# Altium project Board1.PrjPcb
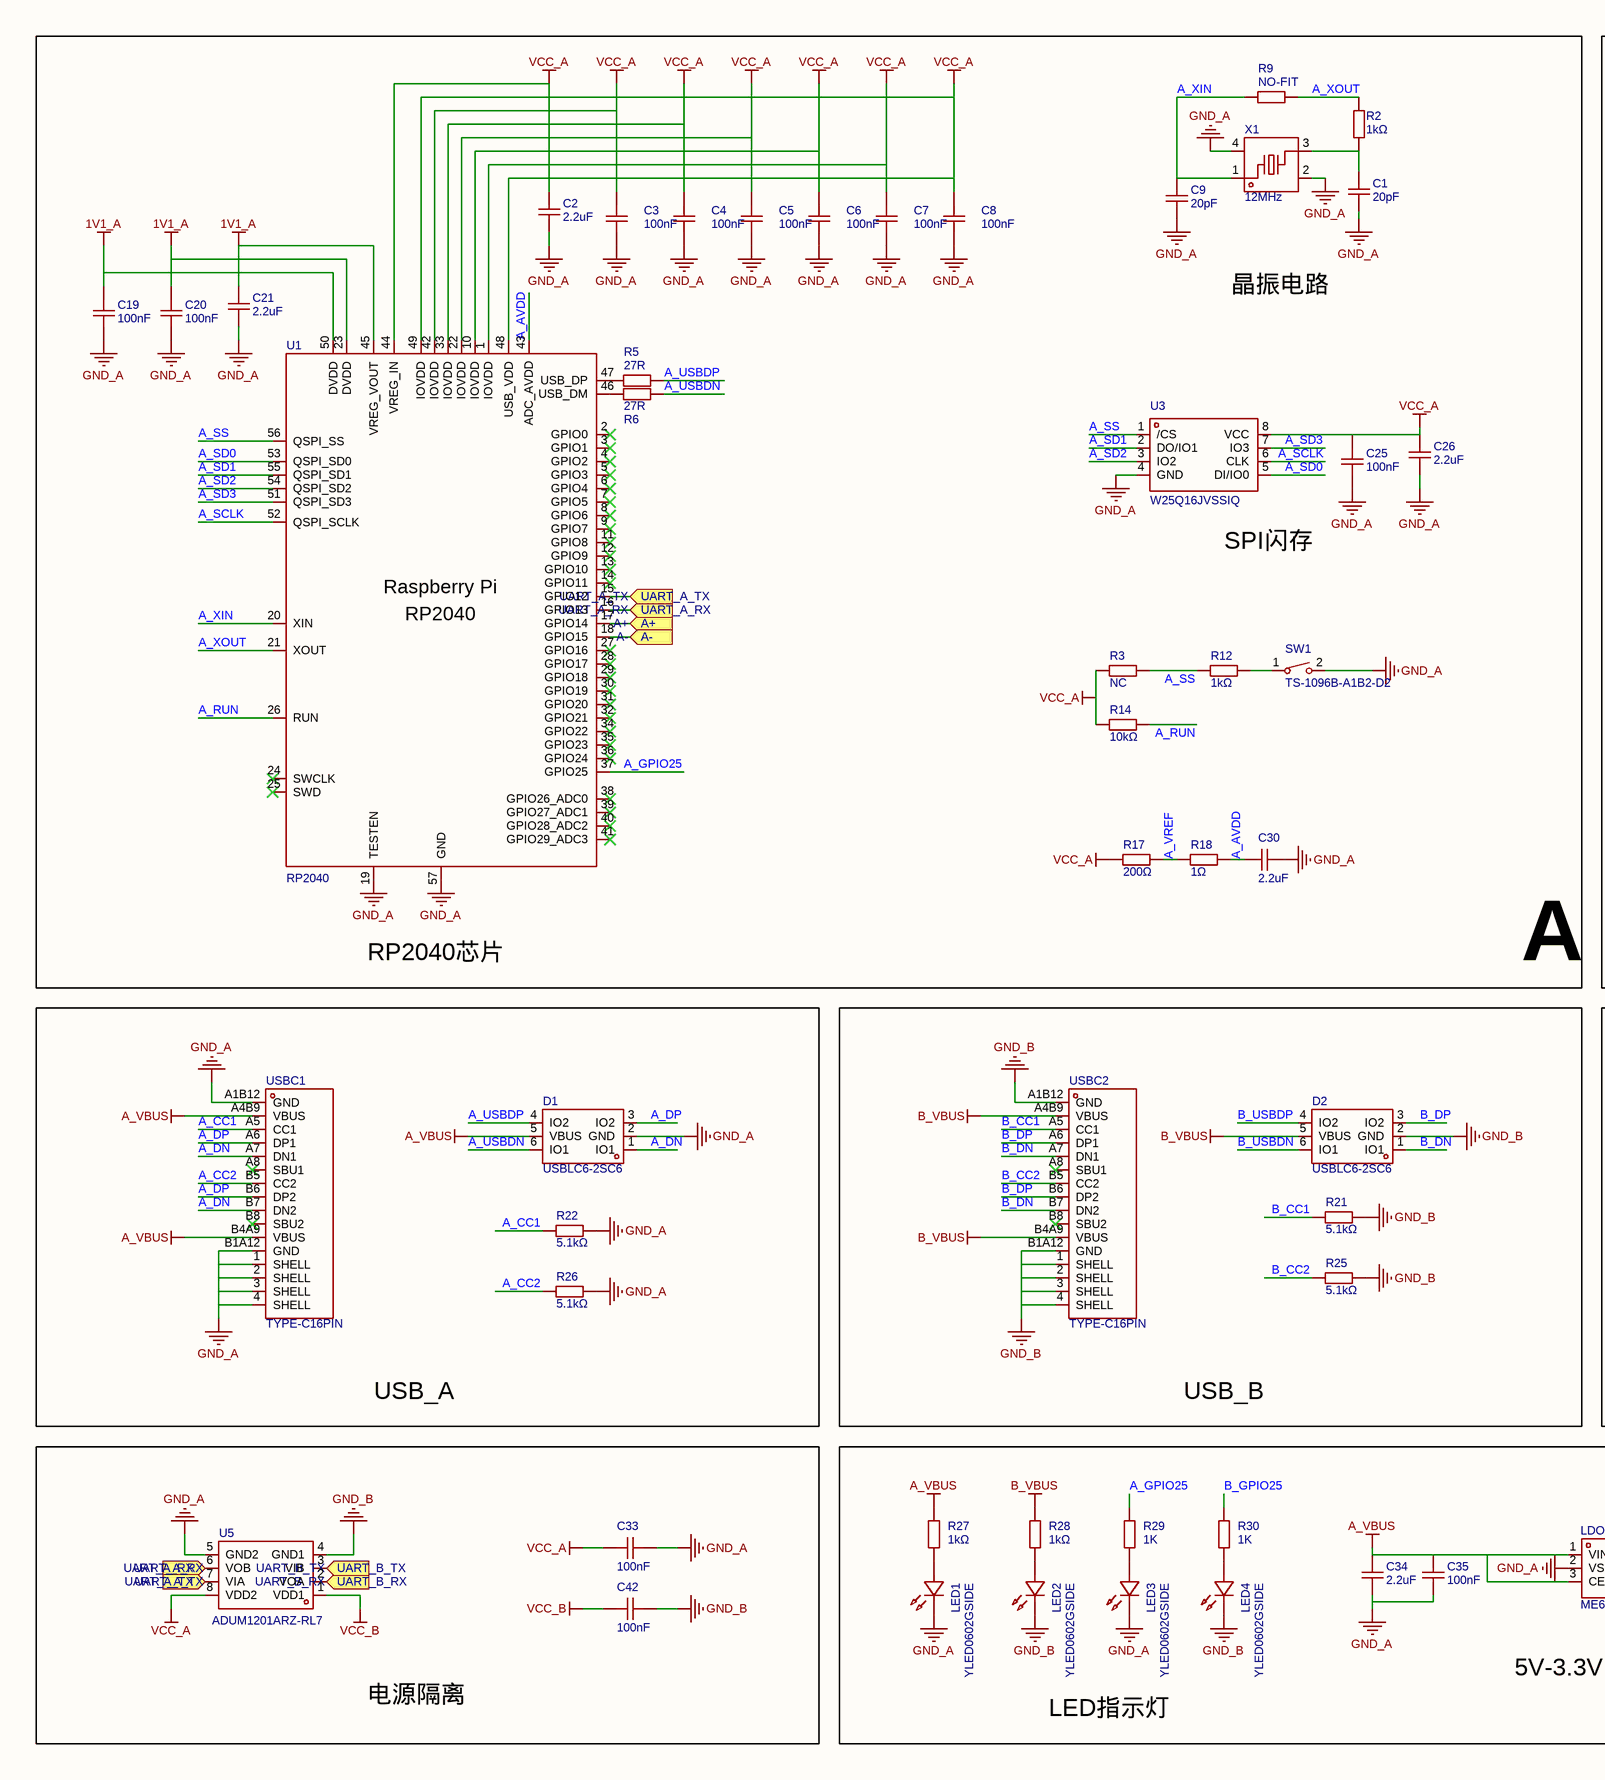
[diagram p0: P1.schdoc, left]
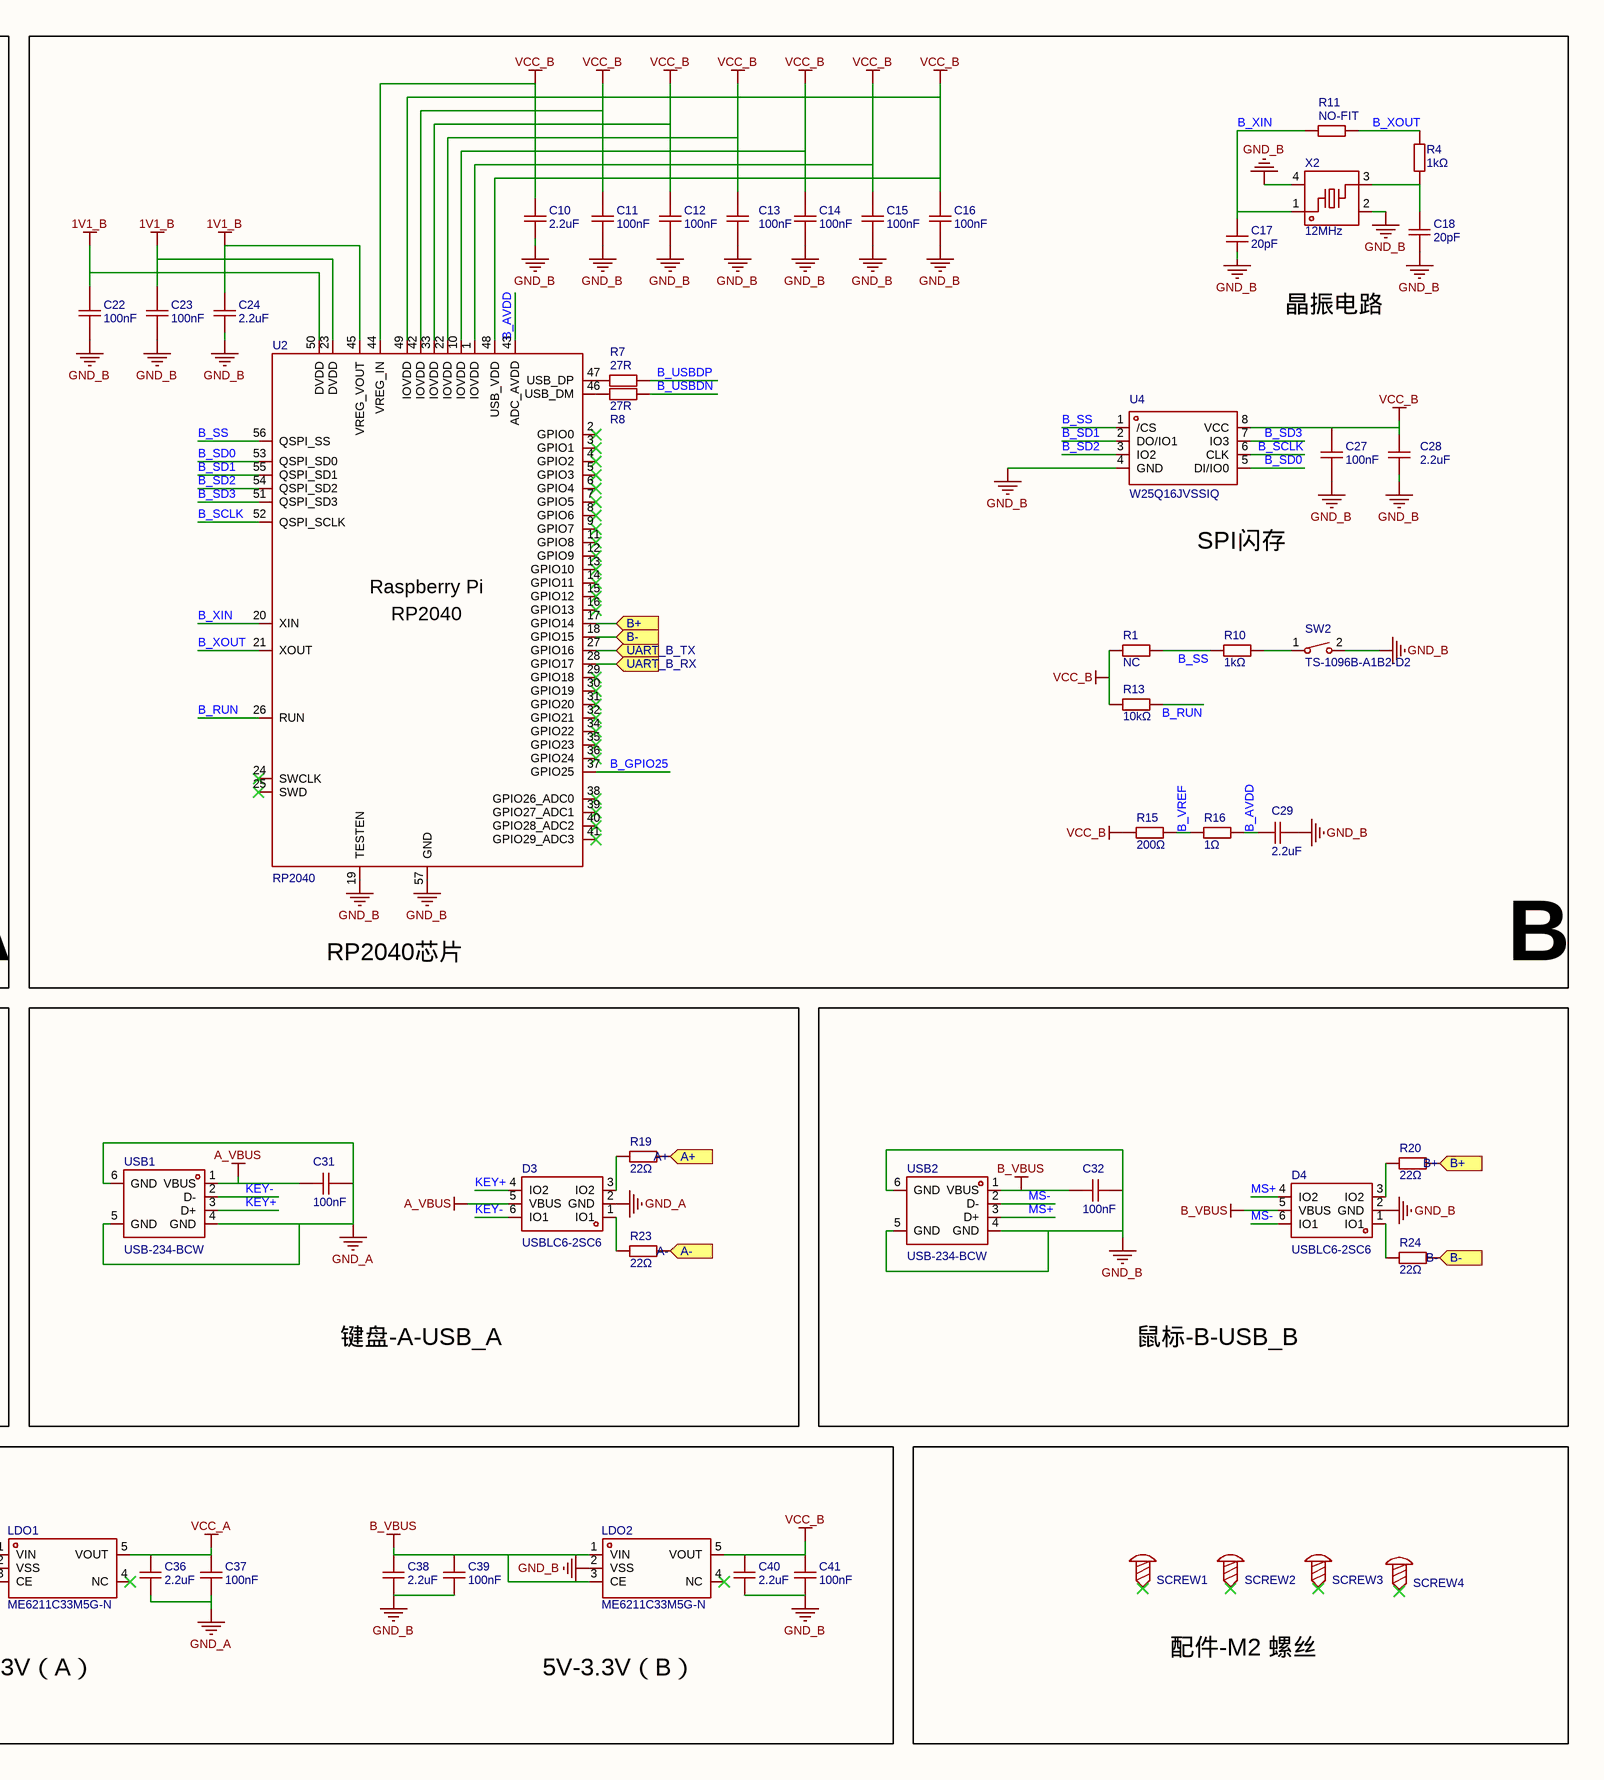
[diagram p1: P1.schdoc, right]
1 sheet, 99 parts. Net scope: flat (ports and power ports of the same name join across sheets).
Board file: PCB1.pcbdoc

## Sheet P1.schdoc
size 594 x 421 mm; Symbol: Sheet-Symbol_A4; Company: 嘉立创EDA; Version: V1.0; Page Size: A4; @Project Name: DESKHOP键盘鼠标共享器; @Page Count: 1; @Update Date: 2026-10-31; @Create Date: 2026-10-31; @Schematic Name: Schematic1; @Page No: 1; @Page Name: P1; Device: Sheet-Symbol_A4

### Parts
C1  20pF  [C0603]
C2  value 2.2uF  [C0603]  (hidden comment: CL10A225KO8NNNC)
C3  value 100nF  [C0603]  (hidden comment: CC0603KRX7R9BB104)
C4  value 100nF  [C0603]  (hidden comment: CC0603KRX7R9BB104)
C5  value 100nF  [C0603]  (hidden comment: CC0603KRX7R9BB104)
C6  value 100nF  [C0603]  (hidden comment: CC0603KRX7R9BB104)
C7  value 100nF  [C0603]  (hidden comment: CC0603KRX7R9BB104)
C8  value 100nF  [C0603]  (hidden comment: CC0603KRX7R9BB104)
C9  20pF  [C0603]
C10  value 2.2uF  [C0603]  (hidden comment: CL10A225KO8NNNC)
C11  value 100nF  [C0603]  (hidden comment: CC0603KRX7R9BB104)
C12  value 100nF  [C0603]  (hidden comment: CC0603KRX7R9BB104)
C13  value 100nF  [C0603]  (hidden comment: CC0603KRX7R9BB104)
C14  value 100nF  [C0603]  (hidden comment: CC0603KRX7R9BB104)
C15  value 100nF  [C0603]  (hidden comment: CC0603KRX7R9BB104)
C16  value 100nF  [C0603]  (hidden comment: CC0603KRX7R9BB104)
C17  20pF  [C0603]
C18  20pF  [C0603]
C19  value 100nF  [C0603]  (hidden comment: CC0603KRX7R9BB104)
C20  100nF  [C0603]
C21  value 2.2uF  [C0603]  (hidden comment: CL10A225KO8NNNC)
C22  value 100nF  [C0603]  (hidden comment: CC0603KRX7R9BB104)
C23  value 100nF  [C0603]  (hidden comment: CC0603KRX7R9BB104)
C24  value 2.2uF  [C0603]  (hidden comment: CL10A225KO8NNNC)
C25  value 100nF  [C0603]  (hidden comment: CC0603KRX7R9BB104)
C26  value 2.2uF  [C0603]  (hidden comment: CL10A225KO8NNNC)
C27  value 100nF  [C0603]  (hidden comment: CC0603KRX7R9BB104)
C28  value 2.2uF  [C0603]  (hidden comment: CL10A225KO8NNNC)
C29  value 2.2uF  [C0603]  (hidden comment: CL10A225KO8NNNC)
C30  value 2.2uF  [C0603]  (hidden comment: CL10A225KO8NNNC)
C31  value 100nF  [C0603]  (hidden comment: CC0603KRX7R9BB104)
C32  value 100nF  [C0603]  (hidden comment: CC0603KRX7R9BB104)
C33  100nF  [C0603]
C34  2.2uF  [C0603]
C35  100nF  [C0603]
C36  2.2uF  [C0603]
C37  100nF  [C0603]
C38  2.2uF  [C0603]
C39  100nF  [C0603]
C40  2.2uF  [C0603]
C41  100nF  [C0603]
C42  100nF  [C0603]
D1  USBLC6-2SC6  [SOT-23-6_L2.9-W1.6-P0.95-LS2.8-BL]
D2  USBLC6-2SC6  [SOT-23-6_L2.9-W1.6-P0.95-LS2.8-BL]
D3  USBLC6-2SC6  [SOT-23-6_L2.9-W1.6-P0.95-LS2.8-BL]
D4  USBLC6-2SC6  [SOT-23-6_L2.9-W1.6-P0.95-LS2.8-BL]
LDO1  ME6211C33M5G-N  [SOT-23-5_L3.0-W1.7-P0.95-LS2.8-BR]
LDO2  ME6211C33M5G-N  [SOT-23-5_L3.0-W1.7-P0.95-LS2.8-BR]
LED1  YLED0602GSIDE  [LED-SMD_L1.6-W1.1-R-RD_GREEN]
LED2  YLED0602GSIDE  [LED-SMD_L1.6-W1.1-R-RD_GREEN]
LED3  YLED0602GSIDE  [LED-SMD_L1.6-W1.1-R-RD_GREEN]
LED4  YLED0602GSIDE  [LED-SMD_L1.6-W1.1-R-RD_GREEN]
R1  value NC  [R0603]  (hidden comment: 0603WAF0000T5E)
R2  1kΩ  [R0603]
R3  value NC  [R0603]  (hidden comment: 0603WAF0000T5E)
R4  1kΩ  [R0603]
R5  27R  [R0603]
R6  27R  [R0603]
R7  27R  [R0603]
R8  27R  [R0603]
R9  NO-FIT  [R0603]
R10  value 1kΩ  [R0603]  (hidden comment: RC0603FR-071KL)
R11  NO-FIT  [R0603]
R12  value 1kΩ  [R0603]  (hidden comment: RC0603FR-071KL)
R13  value 10kΩ  [R0603]  (hidden comment: 0603WAF1002T5E)
R14  value 10kΩ  [R0603]  (hidden comment: 0603WAF1002T5E)
R15  value 200Ω  [R0603]  (hidden comment: 0603WAF2000T5E)
R16  value 1Ω  [R0603]  (hidden comment: 0603WAF100KT5E)
R17  value 200Ω  [R0603]  (hidden comment: 0603WAF2000T5E)
R18  value 1Ω  [R0603]  (hidden comment: 0603WAF100KT5E)
R19  22Ω  [R0603]
R20  22Ω  [R0603]
R21  value 5.1kΩ  [R0603]  (hidden comment: 0603WAF5101T5E)
R22  value 5.1kΩ  [R0603]  (hidden comment: 0603WAF5101T5E)
R23  22Ω  [R0603]
R24  22Ω  [R0603]
R25  value 5.1kΩ  [R0603]  (hidden comment: 0603WAF5101T5E)
R26  value 5.1kΩ  [R0603]  (hidden comment: 0603WAF5101T5E)
R27  1kΩ  [R0603]
R28  value 1kΩ  [R0603]  (hidden comment: 0603WAF1001T5E)
R29  1K  [R0603]
R30  1K  [R0603]
SCREW1  (no value)  [M2螺丝]
SCREW2  (no value)  [M2螺丝]
SCREW3  (no value)  [M2螺丝]
SCREW4  (no value)  [M2螺丝]
SW1  TS-1096B-A1B2-D2  [KEY-TH_L6.0-W3.3-P6.50]
SW2  TS-1096B-A1B2-D2  [KEY-TH_L6.0-W3.3-P6.50]
U1  Manufacturer Part: RP2040  [LQFN-56_L7.0-W7.0-P0.4-EP]  (hidden comment: RP2040_C2040)
U2  Manufacturer Part: RP2040  [LQFN-56_L7.0-W7.0-P0.4-EP]  (hidden comment: RP2040_C2040)
U3  W25Q16JVSSIQ  [SOIC-8_L5.3-W5.3-P1.27-LS8.0-BL]
U4  W25Q16JVSSIQ  [SOIC-8_L5.3-W5.3-P1.27-LS8.0-BL]
U5  ADUM1201ARZ-RL7  [SOIC-8_L4.9-W3.9-P1.27-LS6.0-BL]
USB1  USB-234-BCW  [USB-A-SMD_USB-234-BCW]
USB2  USB-234-BCW  [USB-A-SMD_USB-234-BCW]
USBC1  TYPE-C16PIN  [USB-C-SMD_TYPE-C16PIN]
USBC2  TYPE-C16PIN  [USB-C-SMD_TYPE-C16PIN]
X1  12MHz  [CRYSTAL-SMD_4P-L3.2-W2.5-BL]
X2  12MHz  [CRYSTAL-SMD_4P-L3.2-W2.5-BL]

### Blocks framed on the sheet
A: C1-C9 C19-C21 C25 C26 C30 R2 R3 R5 R6 R9 R12 R14 R17 R18 SW1 U1 U3 X1
B: C10-C18 C22-C24 C27-C29 R1 R4 R7 R8 R10 R11 R13 R15 R16 SW2 U2 U4 X2
USB_A: D1 R22 R26 USBC1
USB_B: D2 R21 R25 USBC2
键盘-A-USB_A: C31 D3 R19 R23 USB1
鼠标-B-USB_B: C32 D4 R20 R24 USB2
电源隔离: C33 C42 U5
配件-M2 螺丝: SCREW1-SCREW4

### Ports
A+ (in), A- (in), B+ (in), B- (in), UART_A_RX (in), UART_A_TX (in), UART_B_RX (in), UART_B_TX (in)

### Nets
1V1_A: C19.2 C20.2 C21.1 U1.23(DVDD) U1.45(VREG_VOUT) U1.50(DVDD)
1V1_B: C22.2 C23.2 C24.1 U2.23(DVDD) U2.45(VREG_VOUT) U2.50(DVDD)
A_VBUS: C31.2 C34.2 C35.2 D1.5(VBUS) D3.5(VBUS) LDO1.1(VIN) LDO1.3(CE) R27.2 USB1.1(VBUS) USBC1.A4B9(VBUS) USBC1.B4A9(VBUS)
B_VBUS: C32.2 C38.2 C39.2 D2.5(VBUS) D4.5(VBUS) LDO2.1(VIN) LDO2.3(CE) R28.2 USB2.1(VBUS) USBC2.A4B9(VBUS) USBC2.B4A9(VBUS)
GND_A: C1.2 C2.2 C3.1 C4.1 C5.1 C6.1 C7.1 C8.1 C9.2 C19.1 C20.1 C21.2 C25.1 C26.2 C30.2 C31.1 C33.2 C34.1 C35.1 C36.1 C37.1 D1.2(GND) D3.2(GND) LDO1.2(VSS) LED1.2(K) LED3.2(K) R22.2 R26.2 SW1.2 U1.19(TESTEN) U1.57(GND) U3.4(GND) U5.5(GND2) USB1.4(GND) USB1.5(GND) USB1.6(GND) USBC1.1(SHELL) USBC1.2(SHELL) USBC1.3(SHELL) USBC1.4(SHELL) USBC1.A1B12(GND) USBC1.B1A12(GND) X1.2(GND) X1.4(GND)
GND_B: C10.2 C11.1 C12.1 C13.1 C14.1 C15.1 C16.1 C17.2 C18.2 C22.1 C23.1 C24.2 C27.1 C28.2 C29.2 C32.1 C38.1 C39.1 C40.1 C41.1 C42.2 D2.2(GND) D4.2(GND) LDO2.2(VSS) LED2.2(K) LED4.2(K) R21.2 R25.2 SW2.2 U2.19(TESTEN) U2.57(GND) U4.4(GND) U5.4(GND1) USB2.4(GND) USB2.5(GND) USB2.6(GND) USBC2.1(SHELL) USBC2.2(SHELL) USBC2.3(SHELL) USBC2.4(SHELL) USBC2.A1B12(GND) USBC2.B1A12(GND) X2.2(GND) X2.4(GND)
VCC_A: C2.1 C3.2 C4.2 C5.2 C6.2 C7.2 C8.2 C25.2 C26.1 C33.1 C36.2 C37.2 LDO1.5(VOUT) R3.2 R14.2 R17.2 U1.1(IOVDD) U1.10(IOVDD) U1.22(IOVDD) U1.33(IOVDD) U1.42(IOVDD) U1.44(VREG_IN) U1.48(USB_VDD) U1.49(IOVDD) U3.8(VCC) U5.8(VDD2)
VCC_B: C10.1 C11.2 C12.2 C13.2 C14.2 C15.2 C16.2 C27.2 C28.1 C40.2 C41.2 C42.1 LDO2.5(VOUT) R1.2 R13.2 R15.2 U2.1(IOVDD) U2.10(IOVDD) U2.22(IOVDD) U2.33(IOVDD) U2.42(IOVDD) U2.44(VREG_IN) U2.48(USB_VDD) U2.49(IOVDD) U4.8(VCC) U5.1(VDD1)
A+: R19.2 U1.17(GPIO14) ; port A+
A-: R23.2 U1.18(GPIO15) ; port A-
A_AVDD: C30.1 R18.1 U1.43(ADC_AVDD)
A_CC1: R22.1 USBC1.A5(CC1)
A_CC2: R26.1 USBC1.B5(CC2)
A_DN: D1.1(IO1) USBC1.A7(DN1) USBC1.B7(DN2)
A_DP: D1.3(IO2) USBC1.A6(DP1) USBC1.B6(DP2)
A_GPIO25: R29.2 U1.37(GPIO25)
A_RUN: R14.1 U1.26(RUN)
A_SCLK: U1.52(QSPI_SCLK) U3.6(CLK)
A_SD0: U1.53(QSPI_SD0) U3.5(DI/IO0)
A_SD1: U1.55(QSPI_SD1) U3.2(DO/IO1)
A_SD2: U1.54(QSPI_SD2) U3.3(IO2)
A_SD3: U1.51(QSPI_SD3) U3.7(IO3)
A_SS: R3.1 R12.2 U1.56(QSPI_SS) U3.1(/CS)
A_USBDN: D1.6(IO1) R6.2
A_USBDP: D1.4(IO2) R5.2
A_VREF: R17.1 R18.2
A_XIN: C9.1 R9.1 U1.20(XIN) X1.1
A_XOUT: R2.2 R9.2 U1.21(XOUT)
B+: R20.2 U2.17(GPIO14) ; port B+
B-: R24.2 U2.18(GPIO15) ; port B-
B_AVDD: C29.1 R16.1 U2.43(ADC_AVDD)
B_CC1: R21.1 USBC2.A5(CC1)
B_CC2: R25.1 USBC2.B5(CC2)
B_DN: D2.1(IO1) USBC2.A7(DN1) USBC2.B7(DN2)
B_DP: D2.3(IO2) USBC2.A6(DP1) USBC2.B6(DP2)
B_GPIO25: R30.2 U2.37(GPIO25)
B_RUN: R13.1 U2.26(RUN)
B_SCLK: U2.52(QSPI_SCLK) U4.6(CLK)
B_SD0: U2.53(QSPI_SD0) U4.5(DI/IO0)
B_SD1: U2.55(QSPI_SD1) U4.2(DO/IO1)
B_SD2: U2.54(QSPI_SD2) U4.3(IO2)
B_SD3: U2.51(QSPI_SD3) U4.7(IO3)
B_SS: R1.1 R10.2 U2.56(QSPI_SS) U4.1(/CS)
B_USBDN: D2.6(IO1) R8.2
B_USBDP: D2.4(IO2) R7.2
B_VREF: R15.1 R16.2
B_XIN: C17.1 R11.1 U2.20(XIN) X2.1
B_XOUT: R4.2 R11.2 U2.21(XOUT)
KEY+: D3.4(IO2) USB1.3(D+)
KEY-: D3.6(IO1) USB1.2(D-)
MS+: D4.4(IO2) USB2.3(D+)
MS-: D4.6(IO1) USB2.2(D-)
UART_A_RX: U1.16(GPIO13) U5.6(VOB) ; port UART_A_RX
UART_A_TX: U1.15(GPIO12) U5.7(VIA) ; port UART_A_TX
UART_B_RX: U2.28(GPIO17) U5.2(VOA) ; port UART_B_RX
UART_B_TX: U2.27(GPIO16) U5.3(VIB) ; port UART_B_TX
NetC1_1: C1.1 R2.1 X1.3
NetC18_1: C18.1 R4.1 X2.3
NetD3_1: D3.1(IO1) R23.1
NetD3_3: D3.3(IO2) R19.1
NetD4_1: D4.1(IO1) R24.1
NetD4_3: D4.3(IO2) R20.1
NetLED1_1: LED1.1(A) R27.1
NetLED2_1: LED2.1(A) R28.1
NetLED3_1: LED3.1(A) R29.1
NetLED4_1: LED4.1(A) R30.1
NetR5_1: R5.1 U1.47(USB_DP)
NetR6_1: R6.1 U1.46(USB_DM)
NetR7_1: R7.1 U2.47(USB_DP)
NetR8_1: R8.1 U2.46(USB_DM)
NetR10_1: R10.1 SW2.1
NetR12_1: R12.1 SW1.1

Not connected (* = marked no-connect by the designer): LDO1 4(NC)*; LDO2 4(NC)*; SCREW1 1*; SCREW2 1*; SCREW3 1*; SCREW4 1*; U1 2(GPIO0)* 3(GPIO1)* 4(GPIO2)* 5(GPIO3)* 6(GPIO4)* 7(GPIO5)* 8(GPIO6)* 9(GPIO7)* 11(GPIO8)* 12(GPIO9)* 13(GPIO10)* 14(GPIO11)* 24(SWCLK)* 25(SWD)* 27(GPIO16)* 28(GPIO17)* 29(GPIO18)* 30(GPIO19)* 31(GPIO20)* 32(GPIO21)* 34(GPIO22)* 35(GPIO23)* 36(GPIO24)* 38(GPIO26_ADC0)* 39(GPIO27_ADC1)* 40(GPIO28_ADC2)* 41(GPIO29_ADC3)*; U2 2(GPIO0)* 3(GPIO1)* 4(GPIO2)* 5(GPIO3)* 6(GPIO4)* 7(GPIO5)* 8(GPIO6)* 9(GPIO7)* 11(GPIO8)* 12(GPIO9)* 13(GPIO10)* 14(GPIO11)* 15(GPIO12)* 16(GPIO13)* 24(SWCLK)* 25(SWD)* 29(GPIO18)* 30(GPIO19)* 31(GPIO20)* 32(GPIO21)* 34(GPIO22)* 35(GPIO23)* 36(GPIO24)* 38(GPIO26_ADC0)* 39(GPIO27_ADC1)* 40(GPIO28_ADC2)* 41(GPIO29_ADC3)*; USBC1 A8(SBU1)* B8(SBU2)*; USBC2 A8(SBU1)* B8(SBU2)*

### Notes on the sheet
- 晶振电路
- SPI闪存
- RP2040芯片
- LED指示灯
- 5V-3.3V（A）
- 5V-3.3V（B）

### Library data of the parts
C1 C9 C17 C18 = CC0603JRNPO9BN150: 容值:15pF;精度:±5%;额定电压:50V;材质(温度系数):NP0;; Manufacturer: YAGEO(国巨); 3D Model: ac125912035d415993ca9572d50418b1; 3D Model Transform: 62.992,31.496,0,0,0,0,0,0,0; Tolerance: ±5%; Voltage Rated: 50V; Temperature Coefficient: NP0; AddInBom: yes; ModelName: C0603_L1.6-W0.8-H0.8
C2 C10 C21 C24 C26 C28-C30 = CL10A225KO8NNNC: 容值:2.2uF;精度:±10%;额定电压:16V;材质(温度系数):X5R;; Manufacturer: SAMSUNG(三星); AddInBom: yes; ModelId: ac125912035d415993ca9572d50418b1; ModelName: C0603_L1.6-W0.8-H0.8; ModelTransform: 62.992,31.496,0,0,0,0,0,0,0; Tolerance: ±10%; Voltage Rated: 16V; Temperature Coefficient: X5R
C3-C8 C11-C16 C19 C22 C23 C25 C27 C31 C32 = CC0603KRX7R9BB104: 容值:100nF;精度:±10%;额定电压:50V;材质(温度系数):X7R;; Manufacturer: YAGEO(国巨); AddInBom: yes; ModelId: ac125912035d415993ca9572d50418b1; ModelName: C0603_L1.6-W0.8-H0.8; ModelTransform: 62.992,31.496,0,0,0,0,0,0,0; Tolerance: ±10%; Voltage Rated: 50V; Temperature Coefficient: X7R
C20 = CC0603KRX7R9BB104: 容值:100nF;精度:±10%;额定电压:50V;材质(温度系数):X7R;; Manufacturer: YAGEO(国巨); 3D Model: ac125912035d415993ca9572d50418b1; 3D Model Transform: 62.992,31.496,0,0,0,0,0,0,0; Tolerance: ±10%; Voltage Rated: 50V; Temperature Coefficient: X7R; AddInBom: yes; ModelName: C0603_L1.6-W0.8-H0.8
C33 C42 = CAP_0603: Symbol: Capacitance; 3D Model: ac125912035d415993ca9572d50418b1; 3D Model Transform: 62.992,31.496,0,0,0,0,0,0,0; ConvertToPcb: yes; ModelName: C0603_L1.6-W0.8-H0.8
C34 C36 C38 C40 = CL10A225KO8NNNC: 容值:2.2uF;精度:±10%;额定电压:16V;材质(温度系数):X5R;; Manufacturer: SAMSUNG(三星); 3D Model: ac125912035d415993ca9572d50418b1; 3D Model Transform: 62.992,31.496,0,0,0,0,0,0,0; Tolerance: ±10%; Voltage Rated: 16V; Temperature Coefficient: X5R; AddInBom: yes; ModelName: C0603_L1.6-W0.8-H0.8
C35 C37 C39 C41 = 0603B104K500NT: 容值:100nF;精度:±10%;额定电压:50V;材质(温度系数):X7R;; Manufacturer: FH(风华); 3D Model: ac125912035d415993ca9572d50418b1; 3D Model Transform: 62.992,31.496,0,0,0,0,0,0,0; Tolerance: ±10%; Voltage Rated: 50V; Temperature Coefficient: X7R; AddInBom: yes; ModelName: C0603_L1.6-W0.8-H0.8
D1-D4 = USBLC6-2SC6_C2827654: 极性:单向;反向截止电压(Vrwm):5V;钳位电压:12V;峰值脉冲电流(Ipp):6A;峰值脉冲功率(Ppp):150W;击穿电压:6V;; Manufacturer: TECH PUBLIC(台舟); AddInBom: yes; ModelId: 18da8f6c14a34920b3e136b5c401a1190819f05c4eef4c71ace90d822a990e87; ModelName: SOT-23-6_L2.9-W1.6-H1.5-LS2.8-P0.95; ModelTransform: 110.236,113.364,0,90,0,0,0.0005,0.0005,0; Polarity: 单向; Reverse Stand-Off Voltage (Vrwm): 5V; Clamping Voltage: 12V; Peak Pulse Current (Ipp): 6A; Peak Pulse Power Dissipation (Ppp): 150W; Voltage - Breakdown: 6V; Reverse Leakage Current (Ir): 80nA; Number of Channels: 双路; level of protection: IEC 61000-4-2；IEC 61000-4-4；IEC 61000-4-5; Type: ESD; Junction Capacitance: 0.35pF
LDO1 LDO2 = ME6211C33M5G-N: 输出类型:固定;输出极性:正;输出通道数:1;最大输入电压:6V;输出电压:3.3V;压差:260mV@(200mA);输出电流:500mA;电源纹波抑制比(PRSS):70dB@(1kHz),62dB@(10kHz);; Manufacturer: MICRONE(南京微盟); 3D Model: 0a2a1b8f50944f73965918ad6e5fe167; 3D Model Transform: 114.173,109.636,0,180,0,0,-0.863,0.863,0; Output Type: 固定; Output Polarity: 正; Number of Outputs: 1; Maximum Input Voltage: 6V; Output Voltage: 3.3V; Output Current: 500mA; AddInBom: yes; ModelName: SOT-23-5_L2.9-W1.6-H1.1-LS2.8-P0.95
LED1-LED4 = YLED0602GSIDE: 灯头类型:1mmx0.75mm方形灯头;发光颜色:翠绿色;正向压降(Vf):2.5V~3.1V;功率:100mW;测试电流:20mA;波长:534nm;二极管配置:独立二极管;透镜颜色:无色透明透镜;色温:-;发光强度:430mcd;发光角度:120°;载带方式:-;工作温度:-40℃~+85℃;; Manufacturer: YONGYUTAI(永裕泰); AddInBom: yes; ModelId: 2c28468672eb41c4bc812ce62ea4e6950819f05c4eef4c71ace90d822a990e87; ModelTransform: 63.7794,43.7007,0,0,0,0,0,11.22,0; Illumination Color: 翠绿色; Power(Watts): 100mW; Test Current: 20mA; Wavelength - Dominant: 534nm; Peak Wavelength: 525nm; Diode Configuration: 独立二极管; Lens Color: 无色透明透镜; Luminous Intensity: 430mcd; Viewing Angle: 120°
R1 R3 = 0603WAF0000T5E: 阻值:0Ω;精度:±1%;功率:100mW;电阻类型:厚膜电阻;; Manufacturer: UNI-ROYAL(厚声); Convert to PCB: no; ModelId: fc143cca1e79419f9cd78b61e9279f08; ModelTransform: 31.8897,63.7794,0,90,0,0,0,0,0; Tolerance: ±1%; Power(Watts): 100mW; Overload Voltage (Max): 75V
R2 R4 = RC0603FR-071KL: 电阻类型:厚膜电阻;阻值:1kΩ;精度:±1%;功率:100mW;温度系数:±100ppm/℃;最大工作电压:75V;工作温度范围:-55℃~+155℃;; Manufacturer: YAGEO(国巨); 3D Model: 3281a289d46d4bb1877be1eabd090e13; 3D Model Transform: 62.992,31.496,0,0,0,0,0,0,0; Tolerance: ±1%; Power(Watts): 100mW; Overload Voltage (Max): 75V; AddInBom: yes; ModelName: R0603_L1.6-W0.8-H0.8
R5-R8 = Res_0603: Symbol: 电阻; 3D Model: fc143cca1e79419f9cd78b61e9279f08; 3D Model Transform: 31.8897,63.7794,0,90,0,0,0,0,0; ConvertToPcb: yes
R9 R11 = RC0603FR-071KL: 电阻类型:厚膜电阻;阻值:1kΩ;精度:±1%;功率:100mW;温度系数:±100ppm/℃;最大工作电压:75V;工作温度范围:-55℃~+155℃;; 3D Model: 3281a289d46d4bb1877be1eabd090e13; 3D Model Transform: 62.992,31.496,0,0,0,0,0,0,0; Convert to PCB: no; ModelName: R0603_L1.6-W0.8-H0.8
R10 R12 = RC0603FR-071KL: 电阻类型:厚膜电阻;阻值:1kΩ;精度:±1%;功率:100mW;; Manufacturer: YAGEO(国巨); AddInBom: yes; ModelId: fc143cca1e79419f9cd78b61e9279f08; ModelTransform: 31.8897,63.7794,0,90,0,0,0,0,0; Tolerance: ±1%; Power(Watts): 100mW; Temperature Coefficient: ±100ppm/℃; Overload Voltage (Max): 75V
R13 R14 = 0603WAF1002T5E: 电阻类型:厚膜电阻;阻值:10kΩ;精度:±1%;功率:100mW;; Manufacturer: UNI-ROYAL(厚声); AddInBom: yes; ModelId: fc143cca1e79419f9cd78b61e9279f08; ModelTransform: 31.8897,63.7794,0,90,0,0,0,0,0; Tolerance: ±1%; Power(Watts): 100mW; Temperature Coefficient: ±100ppm/℃; Overload Voltage (Max): 75V
R15 R17 = 0603WAF2000T5E: 阻值:200Ω;精度:±1%;功率:100mW;温度系数:±100ppm/℃;电阻类型:厚膜电阻;; Manufacturer: UNI-ROYAL(厚声); AddInBom: yes; ModelId: fc143cca1e79419f9cd78b61e9279f08; ModelTransform: 31.8897,63.7794,0,90,0,0,0,0,0; Tolerance: ±1%; Power(Watts): 100mW; Overload Voltage (Max): 75V
R16 R18 = 0603WAF100KT5E: 阻值:1Ω;精度:±1%;功率:100mW;温度系数:±400ppm/℃;电阻类型:厚膜电阻;; Manufacturer: UNI-ROYAL(厚声); AddInBom: yes; ModelId: fc143cca1e79419f9cd78b61e9279f08; ModelTransform: 31.8897,63.7794,0,90,0,0,0,0,0; Tolerance: ±1%; Power(Watts): 100mW; Overload Voltage (Max): 75V
R19 R20 R23 R24 = RC0603FR-0722RL: 电阻类型:厚膜电阻;阻值:22Ω;精度:±1%;功率:100mW;最大工作电压:75V;温度系数:±100ppm/℃;; Manufacturer: YAGEO(国巨); 3D Model: fc143cca1e79419f9cd78b61e9279f08; 3D Model Transform: 31.8897,63.7794,0,90,0,0,0,0,0; Tolerance: ±1%; Power(Watts): 100mW; Overload Voltage (Max): 75V; AddInBom: yes
R21 R22 R25 R26 = 0603WAF5101T5E: 阻值:5.1kΩ;精度:±1%;功率:100mW;温度系数:±100ppm/℃;电阻类型:厚膜电阻;; Manufacturer: UNI-ROYAL(厚声); AddInBom: yes; ModelId: fc143cca1e79419f9cd78b61e9279f08; ModelTransform: 31.8897,63.7794,0,90,0,0,0,0,0; Tolerance: ±1%; Power(Watts): 100mW; Overload Voltage (Max): 75V
R27 R29 R30 = 0603WAF1001T5E: 电阻类型:厚膜电阻;阻值:1kΩ;精度:±1%;功率:100mW;温度系数:±100ppm/℃;; Manufacturer: UNI-ROYAL(厚声); 3D Model: fc143cca1e79419f9cd78b61e9279f08; 3D Model Transform: 31.8897,63.7794,0,90,0,0,0,0,0; Tolerance: ±1%; Power(Watts): 100mW; Overload Voltage (Max): 75V; AddInBom: yes
R28 = 0603WAF1001T5E: 电阻类型:厚膜电阻;阻值:1kΩ;精度:±1%;功率:100mW;温度系数:±100ppm/℃;; Manufacturer: UNI-ROYAL(厚声); AddInBom: yes; ModelId: fc143cca1e79419f9cd78b61e9279f08; ModelTransform: 31.8897,63.7794,0,90,0,0,0,0,0; Tolerance: ±1%; Power(Watts): 100mW; Overload Voltage (Max): 75V
SCREW1-SCREW4 = M2螺丝: Symbol: 螺丝孔; ConvertToPcb: yes
SW1 SW2 = TS-1096B-A1B2-D2: 电路结构:单刀单掷;按钮形状:矩形按钮;作用力:1.8N;安装方式:弯插;开关长度:6mm;开关宽度:3.3mm;开关高度:4.3mm;带支架:不带支架;带灯:无;工作寿命:-;; Manufacturer: Yuandi(元迪); AddInBom: yes; ModelId: 57de0ec0d206456893c1d0b17dfcf6f90819f05c4eef4c71ace90d822a990e87; ModelTransform: 236.22,200.787,0,0,0,0,0,-61.024,-133.858; Circuit: 单刀单掷; Actuator Style: 矩形按钮; Operating Force: 1.8N; Switch Height: 4.3mm; with Bracket: 不带支架; Actuator/Cap Color: 白色; With Lamp: 无
U1 U2 = RP2040_C2040: CPU内核:ARM-M系列;CPU最大主频:133MHz;程序存储容量:-;程序存储器类型:-;GPIO端口数量:30;工作电压范围:-;RAM总容量:264KB;应用领域:-;; Manufacturer: Raspberry Pi(树莓派); AddInBom: yes; ModelId: 6aba77e112f94190bc358c1827f6a3d4; ModelTransform: 276.377,276.377,0,0,0,0,0,0,0; CPU Maximum Speed: 133MHz; GPIO Ports Number: 30; RAM Size: 264KB; ADC (Bit): 12bit; UART/USART: 2; Universal Serial Bus: 有; Peripheral/Function: DMA；PWM
U3 U4 = W25Q16JVSSIQ: 接口类型:SPI;存储容量:16Mbit;; Manufacturer: WINBOND(华邦); AddInBom: yes; ModelId: f83d990ad74f400caf5ac920b7771508; ModelName: SOIC-8_L5.3-W5.3-H1.9-LS7.9-P1.27; ModelTransform: 208.661,311.25654,0,0,0,0,-0.0005,0.0005,0; Interface Type: SPI; Memory Size: 16Mbit; Supply Voltage: 2.7V~3.6V; Page Programming Time (Tpp): 3ms
U5 = ADUM1201ARZ-RL7: 结合高速CMOS和单片变压器技术，这些隔离组件提供了优于光耦合器等替代方案的出色性能。通过避免使用LED和光电二极管，iCoupler设备消除了与光耦合器相关的设计难题。简单的iCoupler数字接口和稳定的性能特性消除了典型光耦合器对不确定电流传输比、非线性传输函数以及温度和寿命影响的担忧。这些iCoupler产品无需外部驱动器和其他分立组件; Manufacturer: ADI(亚德诺); AddInBom: yes; ModelId: e81d2f7d937b4a6ab1dca543ff5d56a40819f05c4eef4c71ace90d822a990e87; ModelName: SOIC-8_L4.9-W3.9-H1.7-LS6.0-P1.27; ModelTransform: 192.913,236.22,0,0,0,0,0,0,0; Number of Forward Channels: 1; Data Rate(Max): 1Mbps; Isolation Voltage(Vrms): 2500; CMTI(kV/us): 25kV/us; Propagation Delay(tpd): 50ns; Voltage - Supply(VCCA): 2.7V~5.5V
USB1 USB2 = USB-234-BCW: 连接器类型:Type-A;协议标准:USB 2.0;公母:母;安装方式:卧贴;触点数量:4P;端口数量:1;额定电流 - 电源:1.5A;工作温度:-20℃~+70℃;; Manufacturer: XUNPU(讯普); AddInBom: yes; ModelId: 634cb1f0688c4f3f93680eb9d60b31c20819f05c4eef4c71ace90d822a990e87; ModelTransform: 633.857,600.393,0,0,0,0,0,-209.156,-19.685; Connector Type: Type-A; Protocol Standard: USB 2.0; Gender: 母; Number of Contacts: 4P; Number of Ports: 1; Current Rating-Power: 1.5A; Voltage Rating: 30V; Connect-Disconnect Life: 5千次; Detection color: 白色
USBC1 USBC2 = TYPE-C16PIN: 连接器类型:Type-C;协议标准:-;公母:母;安装方式:卧贴;触点数量:16P;端口数量:1;额定电流 - 电源:3A;工作温度:-40℃~+85℃;; Manufacturer: SHOU HAN(首韩); AddInBom: yes; ModelId: d6783d3a2268456b863f42d3286191d00819f05c4eef4c71ace90d822a990e87; ModelTransform: 351.9678,311.023,0,180,0,0,0,-41.85,-39.37; Connector Type: Type-C; Gender: 母; Number of Contacts: 16P; Number of Ports: 1; Current Rating-Power: 3A; Voltage Rating: 30V; Connect-Disconnect Life: 1万次; Detection color: 黑色
X1 X2 = XC32M4-12.000-F10NNFT: 晶振类型:贴片无源晶振;频率:12MHz;频率公差:±10ppm;频率稳定度:±10ppm;负载电容:10pF;等效串联电阻(ESR):100Ω;工作温度:-30℃~+85℃;; Manufacturer: HCI(杭晶); 3D Model: ae22b8d143894765bc8100c37cb6356f; 3D Model Transform: 125.984,98.425,0,0,0,0,0,0,0; Crystal Type: 贴片无源晶振; Frequency Tolerance: ±10ppm; Load Capacitance: 10pF; Equivalent Series Resistance (ESR): 100Ω; AddInBom: yes; ModelName: OSC-SMD_4P-L3.2-W2.5-H1.0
